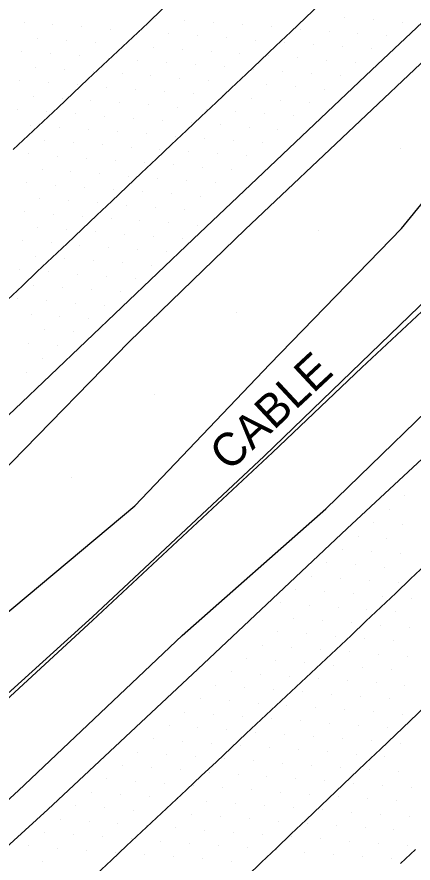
# Model space of a CAD drawing. Extents: x 1548934 to 1561348, y 809680 to 824075.
# Drawn here: x 1552113.3 to 1552161.6, y 810963 to 811066.1 of the extents above; entities that cross this region are included whole.
import ezdxf

# ---------------------------------------------------------------- set-up
doc = ezdxf.new("R2010")
doc.units = 0
for name, color, linetype in [('E_NCDOT_Vertical_Profile_Ground_Line', 7, 'Continuous'), ('Exist DTM QL2 LIDAR Elevation Point', 7, 'Continuous'), ('Exist DTM Scan Elevation Point', 7, 'Continuous'), ('Exist Guardrail Cable Guide Rail', 7, 'Continuous'), ('Exist Guardrail Text', 7, 'Continuous'), ('P_RDY_Terminator_Cell', 7, 'Continuous'), ('PH Exist DTM Breakline', 7, 'Continuous')]:
    doc.layers.add(name, color=color, linetype=linetype)

msp = doc.modelspace()

# ---------------------------------------------------------------- linework, layer by layer
at = {"layer": 'E_NCDOT_Vertical_Profile_Ground_Line'}
for points in [[(1551914.38, 810835.02), (1551936.74, 810855.14), (1551959.05, 810875.31), (1551981.2, 810895.54), (1552003.4, 810915.84), (1552025.39, 810936.24), (1552047.4, 810956.63), (1552069.37, 810977.05), (1552091.26, 810997.73), (1552113.07, 811018.28), (1552134.79, 811038.98), (1552156.58, 811059.6), (1552178.39, 811080.2), (1552200.19, 811100.81)], [(1551914.73, 810783.33), (1551936.97, 810803.47), (1551959.18, 810823.64), (1551981.36, 810843.84), (1552003.23, 810864.39), (1552025.15, 810884.86), (1552043.69, 810901.64), (1552062.11, 810918.55), (1552080.4, 810935.59), (1552098.62, 810952.7), (1552117.11, 810969.53), (1552135.35, 810986.63), (1552153.57, 811003.75), (1552171.88, 811020.77), (1552190.03, 811037.97), (1552208.08, 811055.24), (1552226.13, 811072.47)]]:
    msp.add_lwpolyline(points, dxfattribs=at)
at = {"layer": 'Exist DTM QL2 LIDAR Elevation Point'}
for p, q in [((1552160.03, 811050.01), (1552160.03, 811050.01)), ((1552150.03, 811040.01), (1552150.03, 811040.01)), ((1552140.03, 811030.01), (1552140.03, 811030.01)), ((1552130.03, 811020.01), (1552130.03, 811020.01)), ((1552120.03, 811010.01), (1552120.03, 811010.01))]:
    msp.add_line(p, q, dxfattribs=at)
at = {"layer": 'Exist DTM Scan Elevation Point'}
for p, q in [((1552130.2, 811065.92), (1552130.2, 811065.92)), ((1552153.24, 811065.94), (1552153.24, 811065.94)), ((1552114.2, 811065.36), (1552114.2, 811065.36)), ((1552117.72, 811065.09), (1552117.72, 811065.09)), ((1552121.25, 811064.83), (1552121.25, 811064.83)), ((1552133.72, 811065.65), (1552133.72, 811065.65)), ((1552137.25, 811065.38), (1552137.25, 811065.38)), ((1552140.77, 811065.12), (1552140.77, 811065.12)), ((1552144.3, 811064.85), (1552144.3, 811064.85)), ((1552156.77, 811065.68), (1552156.77, 811065.68)), ((1552160.29, 811065.41), (1552160.29, 811065.41)), ((1552124.77, 811064.56), (1552124.77, 811064.56)), ((1552128.3, 811064.29), (1552128.3, 811064.29)), ((1552131.82, 811064.02), (1552131.82, 811064.02)), ((1552135.35, 811063.76), (1552135.35, 811063.76)), ((1552147.82, 811064.58), (1552147.82, 811064.58)), ((1552151.35, 811064.31), (1552151.35, 811064.31)), ((1552154.87, 811064.05), (1552154.87, 811064.05)), ((1552158.4, 811063.78), (1552158.4, 811063.78)), ((1552115.83, 811063.46), (1552115.83, 811063.46)), ((1552119.35, 811063.2), (1552119.35, 811063.2)), ((1552122.88, 811062.93), (1552122.88, 811062.93)), ((1552126.4, 811062.66), (1552126.4, 811062.66)), ((1552138.87, 811063.49), (1552138.87, 811063.49)), ((1552142.4, 811063.22), (1552142.4, 811063.22)), ((1552145.92, 811062.95), (1552145.92, 811062.95)), ((1552149.45, 811062.69), (1552149.45, 811062.69)), ((1552113.93, 811061.84), (1552113.93, 811061.84)), ((1552129.93, 811062.39), (1552129.93, 811062.39)), ((1552133.45, 811062.13), (1552133.45, 811062.13)), ((1552136.98, 811061.86), (1552136.98, 811061.86)), ((1552152.98, 811062.42), (1552152.98, 811062.42)), ((1552156.5, 811062.15), (1552156.5, 811062.15)), ((1552117.46, 811061.57), (1552117.46, 811061.57)), ((1552120.98, 811061.3), (1552120.98, 811061.3)), ((1552124.51, 811061.03), (1552124.51, 811061.03)), ((1552128.03, 811060.77), (1552128.03, 811060.77)), ((1552140.5, 811061.59), (1552140.5, 811061.59)), ((1552144.03, 811061.32), (1552144.03, 811061.32)), ((1552147.55, 811061.06), (1552147.55, 811061.06)), ((1552151.08, 811060.79), (1552151.08, 811060.79)), ((1552115.56, 811059.94), (1552115.56, 811059.94)), ((1552119.08, 811059.67), (1552119.08, 811059.67)), ((1552131.56, 811060.5), (1552131.56, 811060.5)), ((1552135.08, 811060.23), (1552135.08, 811060.23)), ((1552138.61, 811059.96), (1552138.61, 811059.96)), ((1552142.13, 811059.69), (1552142.13, 811059.69)), ((1552154.61, 811060.52), (1552154.61, 811060.52)), ((1552122.61, 811059.4), (1552122.61, 811059.4)), ((1552126.13, 811059.14), (1552126.13, 811059.14)), ((1552129.66, 811058.87), (1552129.66, 811058.87)), ((1552133.18, 811058.6), (1552133.18, 811058.6)), ((1552145.66, 811059.43), (1552145.66, 811059.43)), ((1552149.18, 811059.16), (1552149.18, 811059.16)), ((1552152.71, 811058.89), (1552152.71, 811058.89)), ((1552113.66, 811058.31), (1552113.66, 811058.31)), ((1552117.19, 811058.04), (1552117.19, 811058.04)), ((1552120.71, 811057.78), (1552120.71, 811057.78)), ((1552124.24, 811057.51), (1552124.24, 811057.51)), ((1552136.71, 811058.33), (1552136.71, 811058.33)), ((1552140.24, 811058.07), (1552140.24, 811058.07)), ((1552143.76, 811057.8), (1552143.76, 811057.8)), ((1552147.29, 811057.53), (1552147.29, 811057.53)), ((1552127.76, 811057.24), (1552127.76, 811057.24)), ((1552131.29, 811056.97), (1552131.29, 811056.97)), ((1552134.81, 811056.7), (1552134.81, 811056.7)), ((1552150.81, 811057.26), (1552150.81, 811057.26)), ((1552115.29, 811056.41), (1552115.29, 811056.41)), ((1552118.82, 811056.15), (1552118.82, 811056.15)), ((1552122.34, 811055.88), (1552122.34, 811055.88)), ((1552125.87, 811055.61), (1552125.87, 811055.61)), ((1552138.34, 811056.44), (1552138.34, 811056.44)), ((1552141.86, 811056.17), (1552141.86, 811056.17)), ((1552145.39, 811055.9), (1552145.39, 811055.9)), ((1552148.92, 811055.64), (1552148.92, 811055.64)), ((1552113.4, 811054.79), (1552113.4, 811054.79)), ((1552116.92, 811054.52), (1552116.92, 811054.52)), ((1552129.39, 811055.34), (1552129.39, 811055.34)), ((1552132.92, 811055.08), (1552132.92, 811055.08)), ((1552136.44, 811054.81), (1552136.44, 811054.81)), ((1552139.97, 811054.54), (1552139.97, 811054.54)), ((1552120.45, 811054.25), (1552120.45, 811054.25)), ((1552123.97, 811053.98), (1552123.97, 811053.98)), ((1552127.5, 811053.71), (1552127.5, 811053.71)), ((1552131.02, 811053.45), (1552131.02, 811053.45)), ((1552143.49, 811054.27), (1552143.49, 811054.27)), ((1552147.02, 811054.01), (1552147.02, 811054.01)), ((1552115.02, 811052.89), (1552115.02, 811052.89)), ((1552118.55, 811052.62), (1552118.55, 811052.62)), ((1552122.07, 811052.35), (1552122.07, 811052.35)), ((1552134.55, 811053.18), (1552134.55, 811053.18)), ((1552138.07, 811052.91), (1552138.07, 811052.91)), ((1552141.6, 811052.64), (1552141.6, 811052.64)), ((1552145.12, 811052.38), (1552145.12, 811052.38)), ((1552125.6, 811052.09), (1552125.6, 811052.09)), ((1552129.12, 811051.82), (1552129.12, 811051.82)), ((1552132.65, 811051.55), (1552132.65, 811051.55)), ((1552116.65, 811050.99), (1552116.65, 811050.99)), ((1552120.18, 811050.72), (1552120.18, 811050.72)), ((1552123.7, 811050.46), (1552123.7, 811050.46)), ((1552136.18, 811051.28), (1552136.18, 811051.28)), ((1552139.7, 811051.02), (1552139.7, 811051.02)), ((1552143.23, 811050.75), (1552143.23, 811050.75)), ((1552114.76, 811049.36), (1552114.76, 811049.36)), ((1552127.23, 811050.19), (1552127.23, 811050.19)), ((1552130.75, 811049.92), (1552130.75, 811049.92)), ((1552134.28, 811049.65), (1552134.28, 811049.65)), ((1552137.8, 811049.39), (1552137.8, 811049.39)), ((1552118.28, 811049.1), (1552118.28, 811049.1)), ((1552121.81, 811048.83), (1552121.81, 811048.83)), ((1552125.33, 811048.56), (1552125.33, 811048.56)), ((1552128.86, 811048.29), (1552128.86, 811048.29)), ((1552141.33, 811049.12), (1552141.33, 811049.12)), ((1552116.39, 811047.47), (1552116.39, 811047.47)), ((1552119.91, 811047.2), (1552119.91, 811047.2)), ((1552132.38, 811048.02), (1552132.38, 811048.02)), ((1552135.91, 811047.76), (1552135.91, 811047.76)), ((1552139.43, 811047.49), (1552139.43, 811047.49)), ((1552123.44, 811046.93), (1552123.44, 811046.93)), ((1552126.96, 811046.66), (1552126.96, 811046.66)), ((1552130.49, 811046.4), (1552130.49, 811046.4)), ((1552114.49, 811045.84), (1552114.49, 811045.84)), ((1552118.01, 811045.57), (1552118.01, 811045.57)), ((1552121.54, 811045.3), (1552121.54, 811045.3)), ((1552134.01, 811046.13), (1552134.01, 811046.13)), ((1552137.54, 811045.86), (1552137.54, 811045.86)), ((1552125.06, 811045.03), (1552125.06, 811045.03)), ((1552128.59, 811044.77), (1552128.59, 811044.77)), ((1552132.12, 811044.5), (1552132.12, 811044.5)), ((1552135.64, 811044.23), (1552135.64, 811044.23)), ((1552116.12, 811043.94), (1552116.12, 811043.94)), ((1552119.64, 811043.67), (1552119.64, 811043.67)), ((1552123.17, 811043.41), (1552123.17, 811043.41)), ((1552126.69, 811043.14), (1552126.69, 811043.14)), ((1552114.22, 811042.31), (1552114.22, 811042.31)), ((1552117.75, 811042.04), (1552117.75, 811042.04)), ((1552130.22, 811042.87), (1552130.22, 811042.87)), ((1552133.74, 811042.6), (1552133.74, 811042.6)), ((1552121.27, 811041.78), (1552121.27, 811041.78)), ((1552124.8, 811041.51), (1552124.8, 811041.51)), ((1552128.32, 811041.24), (1552128.32, 811041.24)), ((1552115.85, 811040.42), (1552115.85, 811040.42)), ((1552119.38, 811040.15), (1552119.38, 811040.15)), ((1552131.85, 811040.97), (1552131.85, 811040.97)), ((1552135.37, 811040.71), (1552135.37, 811040.71)), ((1552122.9, 811039.88), (1552122.9, 811039.88)), ((1552126.43, 811039.61), (1552126.43, 811039.61)), ((1552129.95, 811039.35), (1552129.95, 811039.35)), ((1552133.48, 811039.08), (1552133.48, 811039.08)), ((1552113.95, 811038.79), (1552113.95, 811038.79)), ((1552117.48, 811038.52), (1552117.48, 811038.52)), ((1552121, 811038.25), (1552121, 811038.25)), ((1552124.53, 811037.98), (1552124.53, 811037.98)), ((1552115.58, 811036.89), (1552115.58, 811036.89)), ((1552128.06, 811037.72), (1552128.06, 811037.72)), ((1552131.58, 811037.45), (1552131.58, 811037.45)), ((1552119.11, 811036.62), (1552119.11, 811036.62)), ((1552122.63, 811036.36), (1552122.63, 811036.36)), ((1552126.16, 811036.09), (1552126.16, 811036.09)), ((1552113.69, 811035.26), (1552113.69, 811035.26)), ((1552117.21, 811034.99), (1552117.21, 811034.99)), ((1552129.68, 811035.82), (1552129.68, 811035.82)), ((1552120.74, 811034.73), (1552120.74, 811034.73)), ((1552124.26, 811034.46), (1552124.26, 811034.46)), ((1552127.79, 811034.19), (1552127.79, 811034.19)), ((1552115.32, 811033.36), (1552115.32, 811033.36)), ((1552118.84, 811033.1), (1552118.84, 811033.1)), ((1552122.37, 811032.83), (1552122.37, 811032.83)), ((1552113.42, 811031.74), (1552113.42, 811031.74)), ((1552125.89, 811032.56), (1552125.89, 811032.56)), ((1552116.94, 811031.47), (1552116.94, 811031.47)), ((1552120.47, 811031.2), (1552120.47, 811031.2)), ((1552124, 811030.93), (1552124, 811030.93)), ((1552115.05, 811029.84), (1552115.05, 811029.84)), ((1552118.57, 811029.57), (1552118.57, 811029.57)), ((1552122.1, 811029.3), (1552122.1, 811029.3)), ((1552116.68, 811027.94), (1552116.68, 811027.94)), ((1552120.2, 811027.68), (1552120.2, 811027.68)), ((1552114.78, 811026.31), (1552114.78, 811026.31)), ((1552118.31, 811026.05), (1552118.31, 811026.05)), ((1552116.41, 811024.42), (1552116.41, 811024.42)), ((1552114.51, 811022.79), (1552114.51, 811022.79)), ((1552160.57, 811007.72), (1552160.57, 811007.72)), ((1552158.67, 811006.09), (1552158.67, 811006.09)), ((1552156.78, 811004.46), (1552156.78, 811004.46)), ((1552160.3, 811004.2), (1552160.3, 811004.2)), ((1552154.88, 811002.83), (1552154.88, 811002.83)), ((1552158.4, 811002.57), (1552158.4, 811002.57)), ((1552152.98, 811001.2), (1552152.98, 811001.2)), ((1552156.51, 811000.94), (1552156.51, 811000.94)), ((1552160.03, 811000.67), (1552160.03, 811000.67)), ((1552151.09, 810999.58), (1552151.09, 810999.58)), ((1552154.61, 810999.31), (1552154.61, 810999.31)), ((1552158.14, 810999.04), (1552158.14, 810999.04)), ((1552149.19, 810997.95), (1552149.19, 810997.95)), ((1552152.72, 810997.68), (1552152.72, 810997.68)), ((1552156.24, 810997.41), (1552156.24, 810997.41)), ((1552159.77, 810997.14), (1552159.77, 810997.14)), ((1552147.29, 810996.32), (1552147.29, 810996.32)), ((1552150.82, 810996.05), (1552150.82, 810996.05)), ((1552154.34, 810995.78), (1552154.34, 810995.78)), ((1552145.4, 810994.69), (1552145.4, 810994.69)), ((1552157.87, 810995.52), (1552157.87, 810995.52)), ((1552161.39, 810995.25), (1552161.39, 810995.25)), ((1552148.92, 810994.42), (1552148.92, 810994.42)), ((1552152.45, 810994.15), (1552152.45, 810994.15)), ((1552155.97, 810993.89), (1552155.97, 810993.89)), ((1552159.5, 810993.62), (1552159.5, 810993.62)), ((1552147.03, 810992.79), (1552147.03, 810992.79)), ((1552150.55, 810992.53), (1552150.55, 810992.53)), ((1552154.08, 810992.26), (1552154.08, 810992.26)), ((1552157.6, 810991.99), (1552157.6, 810991.99)), ((1552161.13, 810991.72), (1552161.13, 810991.72)), ((1552145.13, 810991.16), (1552145.13, 810991.16)), ((1552148.66, 810990.9), (1552148.66, 810990.9)), ((1552152.18, 810990.63), (1552152.18, 810990.63)), ((1552143.23, 810989.53), (1552143.23, 810989.53)), ((1552155.71, 810990.36), (1552155.71, 810990.36)), ((1552159.23, 810990.09), (1552159.23, 810990.09)), ((1552146.76, 810989.27), (1552146.76, 810989.27)), ((1552150.28, 810989), (1552150.28, 810989)), ((1552153.81, 810988.73), (1552153.81, 810988.73)), ((1552157.33, 810988.46), (1552157.33, 810988.46)), ((1552141.34, 810987.91), (1552141.34, 810987.91)), ((1552144.86, 810987.64), (1552144.86, 810987.64)), ((1552160.86, 810988.2), (1552160.86, 810988.2)), ((1552148.39, 810987.37), (1552148.39, 810987.37)), ((1552151.91, 810987.1), (1552151.91, 810987.1)), ((1552155.44, 810986.84), (1552155.44, 810986.84)), ((1552158.96, 810986.57), (1552158.96, 810986.57)), ((1552139.44, 810986.28), (1552139.44, 810986.28)), ((1552142.97, 810986.01), (1552142.97, 810986.01)), ((1552146.49, 810985.74), (1552146.49, 810985.74)), ((1552150.02, 810985.47), (1552150.02, 810985.47)), ((1552137.54, 810984.65), (1552137.54, 810984.65)), ((1552141.07, 810984.38), (1552141.07, 810984.38)), ((1552153.54, 810985.21), (1552153.54, 810985.21)), ((1552157.07, 810984.94), (1552157.07, 810984.94)), ((1552160.59, 810984.67), (1552160.59, 810984.67)), ((1552144.6, 810984.11), (1552144.6, 810984.11)), ((1552148.12, 810983.85), (1552148.12, 810983.85)), ((1552151.65, 810983.58), (1552151.65, 810983.58)), ((1552155.17, 810983.31), (1552155.17, 810983.31)), ((1552135.65, 810983.02), (1552135.65, 810983.02)), ((1552139.17, 810982.75), (1552139.17, 810982.75)), ((1552142.7, 810982.48), (1552142.7, 810982.48)), ((1552158.7, 810983.04), (1552158.7, 810983.04)), ((1552133.75, 810981.39), (1552133.75, 810981.39)), ((1552146.22, 810982.22), (1552146.22, 810982.22)), ((1552149.75, 810981.95), (1552149.75, 810981.95)), ((1552153.27, 810981.68), (1552153.27, 810981.68)), ((1552156.8, 810981.41), (1552156.8, 810981.41)), ((1552137.28, 810981.12), (1552137.28, 810981.12)), ((1552140.8, 810980.86), (1552140.8, 810980.86)), ((1552144.33, 810980.59), (1552144.33, 810980.59)), ((1552147.85, 810980.32), (1552147.85, 810980.32)), ((1552160.32, 810981.15), (1552160.32, 810981.15)), ((1552131.86, 810979.76), (1552131.86, 810979.76)), ((1552135.38, 810979.49), (1552135.38, 810979.49)), ((1552138.91, 810979.23), (1552138.91, 810979.23)), ((1552151.38, 810980.05), (1552151.38, 810980.05)), ((1552154.9, 810979.78), (1552154.9, 810979.78)), ((1552158.43, 810979.52), (1552158.43, 810979.52)), ((1552129.96, 810978.13), (1552129.96, 810978.13)), ((1552142.43, 810978.96), (1552142.43, 810978.96)), ((1552145.96, 810978.69), (1552145.96, 810978.69)), ((1552149.48, 810978.42), (1552149.48, 810978.42)), ((1552153.01, 810978.16), (1552153.01, 810978.16)), ((1552133.48, 810977.86), (1552133.48, 810977.86)), ((1552137.01, 810977.6), (1552137.01, 810977.6)), ((1552140.53, 810977.33), (1552140.53, 810977.33)), ((1552156.53, 810977.89), (1552156.53, 810977.89)), ((1552160.06, 810977.62), (1552160.06, 810977.62)), ((1552128.06, 810976.5), (1552128.06, 810976.5)), ((1552131.59, 810976.24), (1552131.59, 810976.24)), ((1552144.06, 810977.06), (1552144.06, 810977.06)), ((1552147.59, 810976.79), (1552147.59, 810976.79)), ((1552151.11, 810976.53), (1552151.11, 810976.53)), ((1552154.64, 810976.26), (1552154.64, 810976.26)), ((1552135.11, 810975.97), (1552135.11, 810975.97)), ((1552138.64, 810975.7), (1552138.64, 810975.7)), ((1552142.16, 810975.43), (1552142.16, 810975.43)), ((1552145.69, 810975.17), (1552145.69, 810975.17)), ((1552158.16, 810975.99), (1552158.16, 810975.99)), ((1552126.17, 810974.87), (1552126.17, 810974.87)), ((1552129.69, 810974.61), (1552129.69, 810974.61)), ((1552133.22, 810974.34), (1552133.22, 810974.34)), ((1552136.74, 810974.07), (1552136.74, 810974.07)), ((1552149.21, 810974.9), (1552149.21, 810974.9)), ((1552152.74, 810974.63), (1552152.74, 810974.63)), ((1552156.26, 810974.36), (1552156.26, 810974.36)), ((1552159.79, 810974.1), (1552159.79, 810974.1)), ((1552124.27, 810973.25), (1552124.27, 810973.25)), ((1552127.8, 810972.98), (1552127.8, 810972.98)), ((1552140.27, 810973.8), (1552140.27, 810973.8)), ((1552143.79, 810973.54), (1552143.79, 810973.54)), ((1552147.32, 810973.27), (1552147.32, 810973.27)), ((1552150.84, 810973), (1552150.84, 810973)), ((1552131.32, 810972.71), (1552131.32, 810972.71)), ((1552134.85, 810972.44), (1552134.85, 810972.44)), ((1552138.37, 810972.18), (1552138.37, 810972.18)), ((1552154.37, 810972.73), (1552154.37, 810972.73)), ((1552157.89, 810972.47), (1552157.89, 810972.47)), ((1552161.42, 810972.2), (1552161.42, 810972.2)), ((1552122.37, 810971.62), (1552122.37, 810971.62)), ((1552125.9, 810971.35), (1552125.9, 810971.35)), ((1552129.42, 810971.08), (1552129.42, 810971.08)), ((1552141.9, 810971.91), (1552141.9, 810971.91)), ((1552145.42, 810971.64), (1552145.42, 810971.64)), ((1552148.95, 810971.37), (1552148.95, 810971.37)), ((1552152.47, 810971.1), (1552152.47, 810971.1)), ((1552120.48, 810969.99), (1552120.48, 810969.99)), ((1552132.95, 810970.81), (1552132.95, 810970.81)), ((1552136.47, 810970.55), (1552136.47, 810970.55)), ((1552140, 810970.28), (1552140, 810970.28)), ((1552143.52, 810970.01), (1552143.52, 810970.01)), ((1552156, 810970.84), (1552156, 810970.84)), ((1552159.52, 810970.57), (1552159.52, 810970.57)), ((1552124, 810969.72), (1552124, 810969.72)), ((1552127.53, 810969.45), (1552127.53, 810969.45)), ((1552131.05, 810969.18), (1552131.05, 810969.18)), ((1552134.58, 810968.92), (1552134.58, 810968.92)), ((1552147.05, 810969.74), (1552147.05, 810969.74)), ((1552150.58, 810969.48), (1552150.58, 810969.48)), ((1552154.1, 810969.21), (1552154.1, 810969.21)), ((1552157.63, 810968.94), (1552157.63, 810968.94)), ((1552118.58, 810968.36), (1552118.58, 810968.36)), ((1552122.11, 810968.09), (1552122.11, 810968.09)), ((1552125.63, 810967.82), (1552125.63, 810967.82)), ((1552138.1, 810968.65), (1552138.1, 810968.65)), ((1552141.63, 810968.38), (1552141.63, 810968.38)), ((1552145.15, 810968.11), (1552145.15, 810968.11)), ((1552148.68, 810967.85), (1552148.68, 810967.85)), ((1552161.15, 810968.67), (1552161.15, 810968.67)), ((1552129.16, 810967.56), (1552129.16, 810967.56)), ((1552132.68, 810967.29), (1552132.68, 810967.29)), ((1552136.21, 810967.02), (1552136.21, 810967.02)), ((1552152.2, 810967.58), (1552152.2, 810967.58)), ((1552155.73, 810967.31), (1552155.73, 810967.31)), ((1552159.25, 810967.04), (1552159.25, 810967.04)), ((1552116.68, 810966.73), (1552116.68, 810966.73)), ((1552120.21, 810966.46), (1552120.21, 810966.46)), ((1552123.73, 810966.19), (1552123.73, 810966.19)), ((1552127.26, 810965.93), (1552127.26, 810965.93)), ((1552139.73, 810966.75), (1552139.73, 810966.75)), ((1552143.26, 810966.49), (1552143.26, 810966.49)), ((1552146.78, 810966.22), (1552146.78, 810966.22)), ((1552150.31, 810965.95), (1552150.31, 810965.95)), ((1552114.79, 810965.1), (1552114.79, 810965.1)), ((1552118.31, 810964.83), (1552118.31, 810964.83)), ((1552130.79, 810965.66), (1552130.79, 810965.66)), ((1552134.31, 810965.39), (1552134.31, 810965.39)), ((1552137.84, 810965.12), (1552137.84, 810965.12)), ((1552141.36, 810964.86), (1552141.36, 810964.86)), ((1552153.83, 810965.68), (1552153.83, 810965.68)), ((1552157.36, 810965.42), (1552157.36, 810965.42)), ((1552160.88, 810965.15), (1552160.88, 810965.15)), ((1552121.84, 810964.57), (1552121.84, 810964.57)), ((1552125.36, 810964.3), (1552125.36, 810964.3)), ((1552128.89, 810964.03), (1552128.89, 810964.03)), ((1552132.41, 810963.76), (1552132.41, 810963.76)), ((1552144.89, 810964.59), (1552144.89, 810964.59)), ((1552148.41, 810964.32), (1552148.41, 810964.32)), ((1552151.94, 810964.05), (1552151.94, 810964.05)), ((1552155.46, 810963.79), (1552155.46, 810963.79)), ((1552116.42, 810963.2), (1552116.42, 810963.2)), ((1552135.94, 810963.5), (1552135.94, 810963.5)), ((1552139.46, 810963.23), (1552139.46, 810963.23)), ((1552158.99, 810963.52), (1552158.99, 810963.52))]:
    msp.add_line(p, q, dxfattribs=at)
at = {"layer": 'Exist Guardrail Cable Guide Rail'}
msp.add_lwpolyline([(1552034.5, 810911), (1552045.54, 810921.16), (1552056.56, 810931.34), (1552067.59, 810941.5), (1552078.58, 810951.71), (1552089.33, 810962.17), (1552100.26, 810972.45), (1552111.51, 810982.37), (1552122.53, 810992.55), (1552133.5, 811002.78), (1552144.46, 811013.02), (1552155.35, 811023.34), (1552166.3, 811033.59), (1552177.23, 811043.86), (1552188.03, 811054.27), (1552198.86, 811064.65), (1552209.7, 811075.02)], dxfattribs=at)
at = {"layer": 'P_RDY_Terminator_Cell'}
for points in [[(1552150.32, 811067.67), (1552148.5, 811065.96), (1552146.69, 811064.24), (1552144.87, 811062.52), (1552143.06, 811060.8), (1552141.24, 811059.09), (1552139.42, 811057.37), (1552137.61, 811055.65), (1552135.79, 811053.93), (1552133.97, 811052.21), (1552132.16, 811050.5), (1552130.34, 811048.78), (1552128.52, 811047.06), (1552126.71, 811045.34), (1552124.89, 811043.63), (1552123.07, 811041.91), (1552121.26, 811040.19), (1552119.44, 811038.47), (1552117.62, 811036.76), (1552115.81, 811035.04), (1552113.99, 811033.32), (1552112.17, 811031.6)], [(1552131.08, 811067.03), (1552129.26, 811065.31), (1552127.44, 811063.6), (1552125.62, 811061.89), (1552123.8, 811060.17), (1552121.98, 811058.46), (1552120.16, 811056.75), (1552118.34, 811055.03), (1552116.52, 811053.32), (1552114.7, 811051.61), (1552112.87, 811049.89)], [(1552123.03, 810961.66), (1552124.85, 810963.37), (1552126.68, 810965.08), (1552128.5, 810966.79), (1552130.32, 810968.5), (1552132.15, 810970.21), (1552133.97, 810971.92), (1552135.79, 810973.63), (1552137.62, 810975.34), (1552139.44, 810977.05), (1552141.26, 810978.76), (1552143.09, 810980.47), (1552144.91, 810982.18), (1552146.74, 810983.89), (1552148.56, 810985.6), (1552150.38, 810987.31), (1552152.21, 810989.02), (1552154.03, 810990.73), (1552155.85, 810992.44), (1552157.67, 810994.16), (1552159.48, 810995.88), (1552161.29, 810997.61), (1552163.11, 810999.33)], [(1552141.32, 810961.38), (1552143.13, 810963.1), (1552144.94, 810964.83), (1552146.75, 810966.55), (1552148.57, 810968.27), (1552150.38, 810969.99), (1552152.19, 810971.71), (1552154, 810973.44), (1552155.81, 810975.16), (1552157.63, 810976.88), (1552159.44, 810978.6), (1552161.25, 810980.33), (1552163.06, 810982.05)], [(1552161.88, 810964.65), (1552160.06, 810962.94)]]:
    msp.add_lwpolyline(points, dxfattribs=at)
at = {"layer": 'PH Exist DTM Breakline'}
for points in [[(1552003.01, 810906.43), (1552015.52, 810918.17), (1552029.54, 810929.99), (1552045.43, 810945.81), (1552058.81, 810959.75), (1552073.18, 810973.42), (1552085.07, 810985.38), (1552097.64, 810997.37), (1552112.65, 811011.79), (1552127.01, 811026.47), (1552141.12, 811040.15), (1552155.14, 811053.41), (1552171.32, 811068.72), (1552188.03, 811084.47), (1552206.02, 811100.25)], [(1552007.43, 810895.1), (1552019.98, 810907.17), (1552033.81, 810919.53), (1552052.67, 810936.3), (1552072.44, 810954.54), (1552082.53, 810964.91), (1552097.03, 810979.12), (1552109.66, 810991.45), (1552127.68, 811006.52), (1552144.15, 811023.77), (1552160.17, 811040.29), (1552177.06, 811060.96), (1552196.62, 811078.95), (1552212.82, 811093.34)], [(1552218.73, 811089.35), (1552201.08, 811070.07), (1552178.52, 811047.99), (1552164.67, 811033.05), (1552143.45, 811012.55), (1552122.54, 810992.99), (1552103.05, 810975.37), (1552087.17, 810959.7), (1552063.93, 810938.51), (1552042.13, 810918.1), (1552024.77, 810903.37), (1552009.2, 810888.66)], [(1552012.08, 810884), (1552029.79, 810897.86), (1552053.55, 810917.03), (1552071.97, 810933.22), (1552094.54, 810954.42), (1552113.52, 810971.84), (1552133.45, 810990.71), (1552150.94, 811006.15), (1552168.7, 811023.35), (1552192.93, 811048.73), (1552219.35, 811074.65), (1552224.76, 811079.94)]]:
    msp.add_lwpolyline(points, dxfattribs=at)

# ---------------------------------------------------------------- texts
at = {"layer": 'Exist Guardrail Text'}
msp.add_text('CABLE', height=4.02, rotation=42.9883, dxfattribs=at).set_placement((1552139.16, 811010.57))

doc.saveas('drawing.dxf')
